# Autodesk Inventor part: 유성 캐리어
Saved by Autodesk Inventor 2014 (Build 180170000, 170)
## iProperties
Created: 2026-05
Part Number: 유성 캐리어
Material: 일반
Document SubType Name: Modeling
Designer: dg
Density: 1 g/cm^3
Appearance: 기본값
Author: dg
Author: jhkim
Creation Date: 2026-05-18
Sending System: Autodesk Inventor 2027
Preprocessor: ST-DEVELOPER v20.1
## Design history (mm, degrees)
node "유성 캐리어1"
node "솔리드1"
node "기준1"
